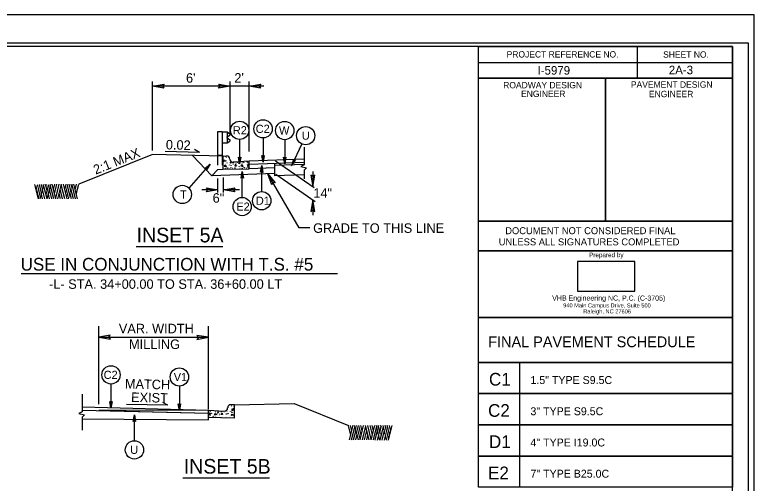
# Model space of a CAD drawing. Extents: x 573748 to 574632, y -54663 to -53209.
# Drawn here: x 574164.6 to 574281, y -53752.5 to -53678.7 of the extents above; entities that cross this region are included whole.
import ezdxf

# ---------------------------------------------------------------- set-up
doc = ezdxf.new("R2010")
doc.units = 0
for name, color, linetype in [('Default', 7, 'Continuous'), ('Prop Dimension', 7, 'Continuous'), ('Prop Dimension Text', 7, 'Continuous'), ('Prop Pavement Schedule Description CELL', 7, 'Continuous'), ('Prop Terminator CELL', 7, 'Continuous'), ('Sheet Cutting Line CELL', 7, 'Continuous'), ('Sheet Data Field CELL', 7, 'Continuous'), ('Sheet Plan CELL', 7, 'Continuous'), ('Sheet Plot Border Inside CELL', 7, 'Continuous'), ('Sheet Plot Border Outside CELL', 7, 'Continuous'), ('Sheet Sticker Exception Certification CELL', 7, 'Continuous'), ('Sheet Typical CELL', 7, 'Continuous'), ('Typical Arrow Superelevation CELL', 7, 'Continuous'), ('Typical Curb CELL', 7, 'Continuous'), ('Typical Guardrail CELL', 7, 'Continuous'), ('Typical Hinge Slope Arterial CELL', 7, 'Continuous'), ('Typical ID Circle CELL', 7, 'Continuous'), ('Typical Pavement Slope CELL', 7, 'Continuous'), ('Typical Slope Point Local CELL', 7, 'Continuous'), ('Typical Terminator CELL', 7, 'Continuous'), ('Typical Text General CELL', 7, 'Continuous'), ('Typical Text ID Circle CELL', 7, 'Continuous'), ('Typical Text Label CELL', 7, 'Continuous')]:
    doc.layers.add(name, color=color, linetype=linetype)

msp = doc.modelspace()

# ---------------------------------------------------------------- linework, layer by layer
at = {"layer": 'Default'}
msp.add_lwpolyline([(574253.15, -53722.26), (574262.18, -53722.26), (574262.18, -53717.54), (574253.15, -53717.54)], close=True, dxfattribs=at)
at = {"layer": 'Prop Dimension'}
for p, q in [((574186.25, -53700.07), (574186.25, -53689.21)), ((574198.47, -53697.35), (574198.47, -53689.21)), ((574201.47, -53700.23), (574201.47, -53689.21)), ((574198.47, -53689.94), (574186.25, -53689.94)), ((574203.78, -53689.94), (574198.47, -53689.94)), ((574210.12, -53699.55), (574210.12, -53702.33)), ((574205.64, -53701.69), (574211.69, -53705.89)), ((574210.12, -53702.28), (574205.53, -53702.45)), ((574210.12, -53702.33), (574209.62, -53702.62)), ((574209.62, -53702.62), (574210.48, -53702.82)), ((574210.48, -53702.82), (574210.12, -53703.17)), ((574210.12, -53703.17), (574210.12, -53704.56)), ((574196.54, -53706.69), (574196.54, -53704.48)), ((574197.43, -53706.69), (574197.43, -53704.33)), ((574205.53, -53704.09), (574205.53, -53703.71)), ((574210.12, -53703.91), (574205.53, -53704.09)), ((574205.68, -53703.81), (574211.86, -53708.11)), ((574211.5, -53703.4), (574211.5, -53705.75)), ((574196.54, -53706.26), (574194.03, -53706.26)), ((574199.94, -53706.26), (574197.43, -53706.26)), ((574211.5, -53707.86), (574211.5, -53710.26)), ((574177.81, -53740.06), (574177.81, -53727.76)), ((574195.05, -53740.82), (574195.05, -53727.76)), ((574177.81, -53729.51), (574195.05, -53729.51)), ((574175.19, -53738.45), (574175.19, -53741.23)), ((574199.15, -53740.15), (574198.6, -53740.14)), ((574199.15, -53740.15), (574208.55, -53739.94)), ((574199.15, -53742.25), (574199.15, -53740.15)), ((574208.55, -53739.94), (574217.09, -53743.39)), ((574175.19, -53741.23), (574174.68, -53741.52)), ((574174.68, -53741.52), (574175.55, -53741.72)), ((574175.55, -53741.72), (574175.19, -53742.07)), ((574195.05, -53740.97), (574177.81, -53741.06)), ((574177.81, -53741.06), (574195.05, -53741.48)), ((574195.05, -53742.14), (574195.05, -53740.97)), ((574195.05, -53740.97), (574197.55, -53741.14)), ((574195.05, -53741.48), (574195.05, -53740.97)), ((574195.08, -53741.68), (574195.27, -53741.43)), ((574195.33, -53741.67), (574195.08, -53741.68)), ((574195.27, -53741.43), (574195.33, -53741.67)), ((574196.01, -53741.77), (574196.15, -53741.53)), ((574196.36, -53741.7), (574196.01, -53741.77)), ((574196.15, -53741.53), (574196.36, -53741.7)), ((574197.03, -53741.69), (574197.22, -53741.44)), ((574197.28, -53741.68), (574197.03, -53741.69)), ((574197.22, -53741.44), (574197.28, -53741.68)), ((574198.08, -53740.65), (574198.08, -53740.63)), ((574198.63, -53741.84), (574198.77, -53741.6)), ((574198.73, -53740.84), (574198.76, -53741.03)), ((574199.05, -53740.94), (574198.73, -53740.84)), ((574198.76, -53741.03), (574199.05, -53740.94)), ((574198.77, -53741.6), (574198.98, -53741.76)), ((574175.19, -53742.07), (574175.19, -53744.12)), ((574175.19, -53742.34), (574195.05, -53742.54)), ((574195.05, -53742.54), (574195.05, -53742.14)), ((574199.15, -53742.25), (574195.05, -53742.14)), ((574198.98, -53741.76), (574198.63, -53741.84)), ((574217.47, -53744.94), (574217.09, -53743.39)), ((574217.29, -53745.67), (574217.85, -53743.38)), ((574217.64, -53744.25), (574217.43, -53743.39)), ((574217.59, -53745.67), (574218.14, -53743.46)), ((574218.69, -53745.67), (574218.12, -53743.39)), ((574218.69, -53744.45), (574218.43, -53743.39)), ((574219.11, -53744.92), (574218.72, -53743.39)), ((574218.92, -53745.67), (574219.48, -53743.39)), ((574219.27, -53744.26), (574219.06, -53743.39)), ((574219.29, -53745.67), (574219.83, -53743.49)), ((574220.36, -53745.67), (574219.8, -53743.39)), ((574220.7, -53745.6), (574220.15, -53743.39)), ((574220.87, -53744.9), (574220.5, -53743.39)), ((574220.68, -53745.67), (574221.25, -53743.39)), ((574221.03, -53744.23), (574220.83, -53743.39)), ((574221.02, -53745.67), (574221.56, -53743.5)), ((574222.06, -53745.71), (574221.49, -53743.42)), ((574222.14, -53744.85), (574221.79, -53743.42)), ((574222.06, -53744.39), (574222.3, -53743.42)), ((574222.07, -53745.71), (574222.61, -53743.54)), ((574222.14, -53743.53), (574222.12, -53743.42)), ((574222.19, -53743.49), (574222.16, -53743.39)), ((574223.15, -53745.71), (574222.58, -53743.42)), ((574223.43, -53745.63), (574222.88, -53743.42)), ((574223.59, -53744.98), (574223.21, -53743.42)), ((574223.41, -53745.71), (574223.98, -53743.41)), ((574223.76, -53744.29), (574223.55, -53743.42)), ((574217.92, -53745.67), (574218.3, -53744.11)), ((574218.24, -53745.67), (574218.46, -53744.77)), ((574218.96, -53745.53), (574218.69, -53744.45)), ((574219.63, -53745.67), (574220, -53744.19)), ((574219.98, -53745.67), (574220.17, -53744.88)), ((574221.33, -53745.71), (574221.69, -53744.22)), ((574221.68, -53745.71), (574221.87, -53744.94)), ((574222.08, -53744.26), (574222.06, -53744.17)), ((574222.42, -53745.71), (574222.78, -53744.22)), ((574222.77, -53745.71), (574222.96, -53744.94))]:
    msp.add_line(p, q, dxfattribs=at)
msp.add_lwpolyline([(574211.04, -53712.28), (574209.33, -53712.28), (574204.39, -53703.76)], dxfattribs=at)
for centre in [(574198.66, -53740.3), (574199.11, -53740.38), (574195.1, -53741.21), (574195.33, -53741.18), (574195.37, -53741.07), (574195.53, -53741.48), (574195.91, -53741.15), (574196.16, -53741.26), (574196.52, -53741.47), (574196.56, -53741.27), (574196.64, -53741.78), (574196.68, -53741.35), (574196.84, -53741.68), (574196.91, -53741.15), (574197.11, -53741.27), (574197.52, -53741.2), (574197.58, -53741.42), (574197.88, -53741.6), (574197.95, -53741.25), (574197.99, -53741.14), (574198.15, -53741.55), (574198.53, -53741.22), (574198.78, -53741.33), (574198.99, -53740.76), (574195.08, -53742.03), (574195.33, -53741.86), (574195.44, -53742.1), (574195.82, -53741.98), (574196.17, -53742.07), (574196.49, -53742.12), (574196.93, -53742.18), (574197.27, -53742.04), (574197.7, -53742.1), (574197.95, -53741.93), (574198.06, -53742.17), (574198.43, -53742.05), (574198.79, -53742.14)]:
    msp.add_circle(centre, 0.0168, dxfattribs=at)
for centre, start, end in [((574198.59, -53740.64), 88.5196, 178.5196), ((574197.58, -53740.63), 266.1351, 358.5196)]:
    msp.add_arc(centre, 0.502, start, end, dxfattribs=at)
at = {"layer": 'Prop Pavement Schedule Description CELL'}
msp.add_lwpolyline([(574237.56, -53726.38), (574277.57, -53726.38), (574277.57, -53733.46), (574237.56, -53733.46)], close=True, dxfattribs=at)
for points in [[(574244.08, -53738.38), (574237.56, -53738.38), (574237.56, -53733.46), (574277.57, -53733.46), (574277.57, -53738.38), (574244.08, -53738.38), (574244.08, -53733.46)], [(574244.08, -53743.3), (574237.56, -53743.3), (574237.56, -53738.38), (574277.57, -53738.38), (574277.57, -53743.3), (574244.08, -53743.3), (574244.08, -53738.38)], [(574244.08, -53748.22), (574237.56, -53748.22), (574237.56, -53743.3), (574277.57, -53743.3), (574277.57, -53748.22), (574244.08, -53748.22), (574244.08, -53743.3)], [(574244.08, -53753.13), (574237.56, -53753.13), (574237.56, -53748.22), (574277.57, -53748.22), (574277.57, -53753.13), (574244.08, -53753.13), (574244.08, -53748.22)]]:
    msp.add_lwpolyline(points, dxfattribs=at)
at = {"layer": 'Prop Terminator CELL'}
for points in [[(574188.05, -53690.27), (574186.25, -53689.94), (574188.07, -53689.64), (574187.83, -53689.96)], [(574196.68, -53689.6), (574198.47, -53689.94), (574196.66, -53690.23), (574196.89, -53689.92)], [(574203.27, -53690.27), (574201.47, -53689.94), (574203.29, -53689.64), (574203.06, -53689.96)], [(574205.02, -53705.47), (574204.39, -53703.76), (574205.57, -53705.16), (574205.18, -53705.12)], [(574211.19, -53703.95), (574211.5, -53705.75), (574211.82, -53703.94), (574211.5, -53704.17)], [(574194.74, -53705.93), (574196.54, -53706.26), (574194.73, -53706.56), (574194.96, -53706.24)], [(574199.23, -53706.6), (574197.43, -53706.26), (574199.24, -53705.97), (574199.01, -53706.28)], [(574211.81, -53709.66), (574211.5, -53707.86), (574211.18, -53709.67), (574211.5, -53709.44)], [(574179.61, -53729.17), (574177.81, -53729.51), (574179.63, -53729.8), (574179.39, -53729.49)], [(574193.25, -53729.84), (574195.05, -53729.51), (574193.23, -53729.21), (574193.47, -53729.53)]]:
    msp.add_lwpolyline(points, close=True, dxfattribs=at)
at = {"layer": 'Sheet Cutting Line CELL'}
msp.add_line((574280.97, -53678.68), (573944.17, -53678.68), dxfattribs=at)
at = {"layer": 'Sheet Plan CELL'}
msp.add_lwpolyline([(574237.56, -53715.89), (574277.57, -53715.89), (574277.57, -53726.38), (574237.56, -53726.38)], close=True, dxfattribs=at)
at = {"layer": 'Sheet Plot Border Inside CELL'}
msp.add_lwpolyline([(574280.07, -53683.17), (573946.77, -53683.17), (573946.77, -53894.19), (574280.07, -53894.19)], close=True, dxfattribs=at)
at = {"layer": 'Sheet Plot Border Outside CELL'}
msp.add_lwpolyline([(574280.97, -53678.68), (573944.17, -53678.68), (573944.17, -53898.68), (574280.97, -53898.68)], close=True, dxfattribs=at)
at = {"layer": 'Sheet Sticker Exception Certification CELL'}
for p, q in [((574237.56, -53715.89), (574237.56, -53711.19)), ((574237.56, -53711.19), (574277.57, -53711.19)), ((574277.57, -53711.2), (574277.57, -53715.9)), ((574277.57, -53715.89), (574237.56, -53715.89))]:
    msp.add_line(p, q, dxfattribs=at)
at = {"layer": 'Sheet Typical CELL'}
for p, q in [((574262.57, -53683.69), (574262.57, -53688.69)), ((574237.56, -53686.19), (574277.57, -53686.19)), ((574257.57, -53688.69), (574257.57, -53711.18))]:
    msp.add_line(p, q, dxfattribs=at)
for points in [[(574277.57, -53683.68), (573977.57, -53683.68), (573977.57, -53893.68), (574277.57, -53893.68)], [(574237.56, -53683.68), (574277.57, -53683.68), (574277.57, -53688.69), (574237.56, -53688.69)], [(574237.56, -53688.69), (574257.57, -53688.69), (574257.57, -53711.19), (574237.56, -53711.19)], [(574257.57, -53688.69), (574277.57, -53688.69), (574277.57, -53711.19), (574257.57, -53711.19)]]:
    msp.add_lwpolyline(points, close=True, dxfattribs=at)
at = {"layer": 'Typical Arrow Superelevation CELL'}
for p, q in [((574193.64, -53700.37), (574188.24, -53700.23)), ((574193.64, -53700.37), (574192.86, -53699.89)), ((574188.67, -53740.23), (574182.15, -53740.08)), ((574188.67, -53740.23), (574187.89, -53739.76))]:
    msp.add_line(p, q, dxfattribs=at)
at = {"layer": 'Typical Curb CELL'}
for p, q in [((574197.38, -53700.95), (574197.92, -53700.93)), ((574197.38, -53703.04), (574197.38, -53700.95)), ((574197.47, -53701.74), (574197.79, -53701.63)), ((574197.76, -53701.82), (574197.47, -53701.74)), ((574197.79, -53701.63), (574197.76, -53701.82)), ((574198.44, -53701.44), (574198.44, -53701.42)), ((574201.47, -53701.76), (574198.97, -53701.93)), ((574201.47, -53702.94), (574201.47, -53701.76)), ((574196.54, -53703.06), (574197.38, -53703.04)), ((574197.38, -53703.04), (574201.47, -53702.94)), ((574197.75, -53702.4), (574197.54, -53702.56)), ((574197.54, -53702.56), (574197.89, -53702.63)), ((574197.89, -53702.63), (574197.75, -53702.4)), ((574199.3, -53702.24), (574199.24, -53702.48)), ((574199.24, -53702.48), (574199.49, -53702.48)), ((574199.49, -53702.48), (574199.3, -53702.24)), ((574200.37, -53702.33), (574200.16, -53702.49)), ((574200.16, -53702.49), (574200.51, -53702.57)), ((574200.51, -53702.57), (574200.37, -53702.33)), ((574201.25, -53702.22), (574201.19, -53702.46)), ((574201.19, -53702.46), (574201.44, -53702.47)), ((574201.44, -53702.47), (574201.25, -53702.22))]:
    msp.add_line(p, q, dxfattribs=at)
for centre in [(574197.41, -53701.18), (574197.53, -53701.56), (574197.75, -53702.12), (574197.86, -53701.09), (574197.99, -53702.01), (574198.53, -53701.94), (574198.57, -53702.04), (574199, -53702), (574199.41, -53702.07), (574199.61, -53701.95), (574199.84, -53702.14), (574199.96, -53702.06), (574200.36, -53702.05), (574200.61, -53701.94), (574201.15, -53701.87), (574201.19, -53701.97), (574201.43, -53702), (574197.73, -53702.94), (574198.09, -53702.84), (574198.37, -53702.35), (574198.46, -53702.97), (574198.58, -53702.72), (574198.64, -53702.4), (574198.82, -53702.9), (574198.94, -53702.21), (574199.25, -53702.84), (574199.59, -53702.97), (574199.68, -53702.48), (574199.89, -53702.57), (574200, -53702.27), (574200.03, -53702.91), (574200.35, -53702.87), (574200.7, -53702.78), (574200.99, -53702.28), (574201.08, -53702.9), (574201.19, -53702.66), (574201.44, -53702.83)]:
    msp.add_circle(centre, 0.0168, dxfattribs=at)
for centre, start, end in [((574197.93, -53701.43), 1.4804, 91.4804), ((574198.94, -53701.43), 181.4804, 273.8649)]:
    msp.add_arc(centre, 0.502, start, end, dxfattribs=at)
at = {"layer": 'Typical Guardrail CELL'}
for p, q in [((574197.24, -53697.14), (574196.5, -53697.14)), ((574196.5, -53697.14), (574196.5, -53700.87)), ((574197.24, -53697.14), (574197.24, -53700.87)), ((574197.24, -53697.14), (574197.99, -53697.14)), ((574197.99, -53697.14), (574197.99, -53698.88)), ((574197.99, -53697.14), (574198.42, -53697.45)), ((574197.99, -53697.94), (574198.42, -53697.64)), ((574197.99, -53698.01), (574197.99, -53697.94)), ((574197.99, -53698.01), (574197.99, -53698.08)), ((574197.99, -53698.08), (574198.42, -53698.39)), ((574197.99, -53698.88), (574198.42, -53698.58)), ((574197.24, -53698.88), (574197.99, -53698.88)), ((574197.24, -53700.87), (574196.5, -53700.87)), ((574196.5, -53700.87), (574196.5, -53702.39)), ((574197.24, -53700.87), (574197.24, -53702.39))]:
    msp.add_line(p, q, dxfattribs=at)
for centre, start, end in [((574198.36, -53697.54), 304.9888, 54.997), ((574198.36, -53698.48), 304.9634, 54.9941)]:
    msp.add_arc(centre, 0.116, start, end, dxfattribs=at)
at = {"layer": 'Typical Hinge Slope Arterial CELL'}
msp.add_line((574186.25, -53700.7), (574174.64, -53705.39), dxfattribs=at)
at = {"layer": 'Typical ID Circle CELL'}
for p, q in [((574199.97, -53698.33), (574199.97, -53702.16)), ((574203.66, -53698.1), (574203.66, -53701.93)), ((574207.07, -53698.37), (574207.07, -53702.19)), ((574209.76, -53699.04), (574208.15, -53702.5)), ((574192.01, -53706.03), (574195.32, -53702.21)), ((574203.45, -53706.54), (574203.45, -53702.46)), ((574200.37, -53707.47), (574200.37, -53703.39)), ((574179.72, -53736.87), (574179.72, -53740.7)), ((574190.49, -53737.21), (574190.49, -53741.03)), ((574183.41, -53745.81), (574183.41, -53741.72))]:
    msp.add_line(p, q, dxfattribs=at)
for centre in [(574199.97, -53696.89), (574203.66, -53696.66), (574207.07, -53696.93), (574210.37, -53697.73), (574190.94, -53707), (574203.45, -53707.99), (574200.37, -53708.91), (574179.72, -53735.43), (574190.49, -53735.76), (574183.41, -53747.25)]:
    msp.add_circle(centre, 1.44, dxfattribs=at)
at = {"layer": 'Typical Pavement Slope CELL'}
for p, q in [((574197.38, -53700.95), (574186.25, -53700.7)), ((574195.58, -53704.09), (574192.56, -53700.84)), ((574210.12, -53701.44), (574201.47, -53701.76)), ((574210.12, -53701.95), (574201.47, -53702.28)), ((574205.53, -53703.71), (574205.53, -53702.12)), ((574195.58, -53704.09), (574196.54, -53703.06)), ((574205.53, -53702.78), (574201.47, -53702.94)), ((574205.53, -53703.71), (574195.58, -53704.09)), ((574175.19, -53740.49), (574195.05, -53740.97)), ((574175.19, -53741), (574195.05, -53741.48))]:
    msp.add_line(p, q, dxfattribs=at)
at = {"layer": 'Typical Slope Point Local CELL'}
for p, q in [((574168.31, -53707.71), (574167.75, -53705.41)), ((574167.96, -53706.29), (574168.18, -53705.42)), ((574168.13, -53706.98), (574168.52, -53705.42)), ((574168.3, -53707.63), (574168.85, -53705.42)), ((574168.57, -53707.71), (574169.15, -53705.42)), ((574169.66, -53707.71), (574169.12, -53705.54)), ((574169.67, -53706.39), (574169.43, -53705.42)), ((574169.54, -53705.49), (574169.57, -53705.39)), ((574169.58, -53706.85), (574169.94, -53705.42)), ((574169.58, -53705.53), (574169.61, -53705.42)), ((574169.66, -53707.71), (574170.24, -53705.42)), ((574170.7, -53707.67), (574170.17, -53705.5)), ((574171.04, -53707.67), (574170.48, -53705.39)), ((574170.69, -53706.23), (574170.9, -53705.39)), ((574170.85, -53706.9), (574171.22, -53705.39)), ((574171.03, -53707.6), (574171.57, -53705.39)), ((574171.36, -53707.67), (574171.93, -53705.39)), ((574172.44, -53707.67), (574171.9, -53705.49)), ((574172.81, -53707.67), (574172.24, -53705.39)), ((574172.46, -53706.26), (574172.67, -53705.39)), ((574172.62, -53706.92), (574173, -53705.39)), ((574173.04, -53706.45), (574173.3, -53705.39)), ((574173.04, -53707.67), (574173.61, -53705.39)), ((574174.14, -53707.67), (574173.59, -53705.46)), ((574174.44, -53707.67), (574173.88, -53705.38)), ((574174.09, -53706.25), (574174.3, -53705.39)), ((574174.26, -53706.94), (574174.64, -53705.39)), ((574169.31, -53707.71), (574168.94, -53706.22)), ((574169.65, -53706.26), (574169.67, -53706.17)), ((574170.4, -53707.71), (574170.03, -53706.22)), ((574172.09, -53707.67), (574171.73, -53706.19)), ((574172.77, -53707.53), (574173.04, -53706.45)), ((574173.48, -53707.67), (574173.26, -53706.77)), ((574173.8, -53707.67), (574173.42, -53706.11)), ((574168.95, -53707.71), (574168.77, -53706.94)), ((574170.04, -53707.71), (574169.86, -53706.94)), ((574171.75, -53707.67), (574171.56, -53706.88))]:
    msp.add_line(p, q, dxfattribs=at)
at = {"layer": 'Typical Terminator CELL'}
for points in [[(574203.84, -53700.87), (574203.66, -53701.93), (574203.47, -53700.87), (574203.66, -53701)], [(574200.16, -53701.1), (574199.97, -53702.16), (574199.79, -53701.1), (574199.97, -53701.23)], [(574207.25, -53701.14), (574207.07, -53702.19), (574206.88, -53701.13), (574207.07, -53701.27)], [(574208.43, -53701.47), (574208.15, -53702.5), (574208.76, -53701.62), (574208.54, -53701.67)], [(574194.49, -53702.89), (574195.32, -53702.21), (574194.76, -53703.13), (574194.71, -53702.91)], [(574203.27, -53703.51), (574203.45, -53702.46), (574203.64, -53703.52), (574203.45, -53703.38)], [(574200.19, -53704.44), (574200.37, -53703.39), (574200.56, -53704.45), (574200.37, -53704.31)], [(574179.9, -53739.64), (574179.72, -53740.7), (574179.54, -53739.64), (574179.72, -53739.77)], [(574190.67, -53739.98), (574190.49, -53741.03), (574190.3, -53739.97), (574190.49, -53740.11)], [(574183.23, -53742.78), (574183.41, -53741.72), (574183.6, -53742.79), (574183.41, -53742.65)]]:
    msp.add_lwpolyline(points, close=True, dxfattribs=at)
at = {"layer": 'Typical Text General CELL'}
msp.add_line((574215.4, -53719.5), (574165.58, -53719.5), dxfattribs=at)
at = {"layer": 'Typical Text Label CELL'}
for p, q in [((574197.32, -53715.27), (574183.66, -53715.27)), ((574204.67, -53751.71), (574191.01, -53751.71))]:
    msp.add_line(p, q, dxfattribs=at)

# ---------------------------------------------------------------- texts
at = {"layer": 'Default'}
for s, height, rotation, p in [('Prepared by', 0.7214, 360, (574254.98, -53716.89)), ('VHB Engineering NC, P.C. (C-3705)', 0.8, 359.9612, (574249.17, -53723.72)), ('940 Main Campus Drive, Suite 500', 0.6436, 359.9612, (574250.9, -53724.8)), ('Raleigh, NC 27606', 0.6436, 359.9612, (574254.06, -53725.74))]:
    msp.add_text(s, height=height, rotation=rotation, dxfattribs=at).set_placement(p)
at = {"layer": 'Prop Dimension'}
msp.add_text('GRADE TO THIS LINE', height=1.5, rotation=360, dxfattribs=at).set_placement((574211.54, -53713.05))
at = {"layer": 'Prop Dimension Text'}
for s, height, p in [("6'", 1.5, (574191.53, -53689.39)), ("2'", 1.5, (574199.14, -53689.38)), ('6"', 1.5, (574195.72, -53708.3)), ('14"', 1.5, (574211.57, -53707.53)), ('INSET 5A', 2.3, (574183.76, -53714.55)), ('VAR. WIDTH', 1.5, (574180.95, -53728.88)), ('MILLING', 1.5, (574182.56, -53731.35)), ('INSET 5B', 2.3, (574191.18, -53750.99))]:
    msp.add_text(s, height=height, dxfattribs=at).set_placement(p)
for s, rotation, p in [('0.02', 358.4883, (574188.34, -53699.89)), ('2:1 MAX', 21.9988, (574177.31, -53703.89)), ('MATCH', 358.6506, (574181.89, -53737.57)), ('EXIST', 358.6506, (574182.87, -53739.69))]:
    msp.add_text(s, height=1.5, rotation=rotation, dxfattribs=at).set_placement(p)
at = {"layer": 'Prop Pavement Schedule Description CELL'}
for s, height, p in [('FINAL PAVEMENT SCHEDULE', 1.7, (574239.11, -53731.07)), ('C1', 2, (574239.22, -53737.12)), ('1.5" TYPE S9.5C', 1.25, (574245.75, -53736.87)), ('C2', 2, (574239.08, -53742.04)), ('3" TYPE S9.5C', 1.25, (574245.75, -53741.79)), ('D1', 2, (574239.22, -53746.96)), ('4" TYPE I19.0C', 1.25, (574245.75, -53746.71)), ('E2', 2, (574239.08, -53751.88)), ('7" TYPE B25.0C', 1.25, (574245.75, -53751.63))]:
    msp.add_text(s, height=height, dxfattribs=at).set_placement(p)
at = {"layer": 'Sheet Data Field CELL'}
for s, p in [('I-5979', (574246.87, -53688.12)), ('2A-3', (574267.53, -53688.06))]:
    msp.add_text(s, height=1.35, dxfattribs=at).set_placement(p)
at = {"layer": 'Sheet Sticker Exception Certification CELL'}
for s, p in [('DOCUMENT NOT CONSIDERED FINAL', (574241.78, -53713.26)), ('UNLESS ALL SIGNATURES COMPLETED', (574240.76, -53715.02))]:
    msp.add_text(s, height=1.1, dxfattribs=at).set_placement(p)
at = {"layer": 'Sheet Typical CELL'}
for s, p in [('PROJECT REFERENCE NO.', (574242, -53685.42)), ('SHEET NO.', (574266.63, -53685.44)), ('ROADWAY DESIGN', (574241.46, -53690.27)), ('PAVEMENT DESIGN', (574261.56, -53690.18)), ('ENGINEER', (574244.27, -53691.64)), ('ENGINEER', (574264.4, -53691.67))]:
    msp.add_text(s, height=1, dxfattribs=at).set_placement(p)
at = {"layer": 'Typical Text General CELL'}
for s, height, p in [('USE IN CONJUNCTION WITH T.S. #5', 2, (574165.5, -53719)), ('-L- STA. 34+00.00 TO STA. 36+60.00 LT', 1.5, (574169.98, -53721.87))]:
    msp.add_text(s, height=height, dxfattribs=at).set_placement(p)
at = {"layer": 'Typical Text ID Circle CELL'}
for s, height, p in [('R2', 1.291, (574198.9, -53697.53)), ('C2', 1.291, (574202.5, -53697.3)), ('W', 1.29, (574206.17, -53697.57)), ('U', 1.29, (574209.76, -53698.37)), ('T', 1.29, (574190.59, -53707.65)), ('D1', 1.291, (574202.52, -53708.63)), ('E2', 1.291, (574199.44, -53709.56)), ('C2', 1.291, (574178.56, -53736.07)), ('V1', 1.291, (574189.6, -53736.41)), ('U', 1.29, (574182.74, -53747.89))]:
    msp.add_text(s, height=height, dxfattribs=at).set_placement(p)

doc.saveas('drawing.dxf')
